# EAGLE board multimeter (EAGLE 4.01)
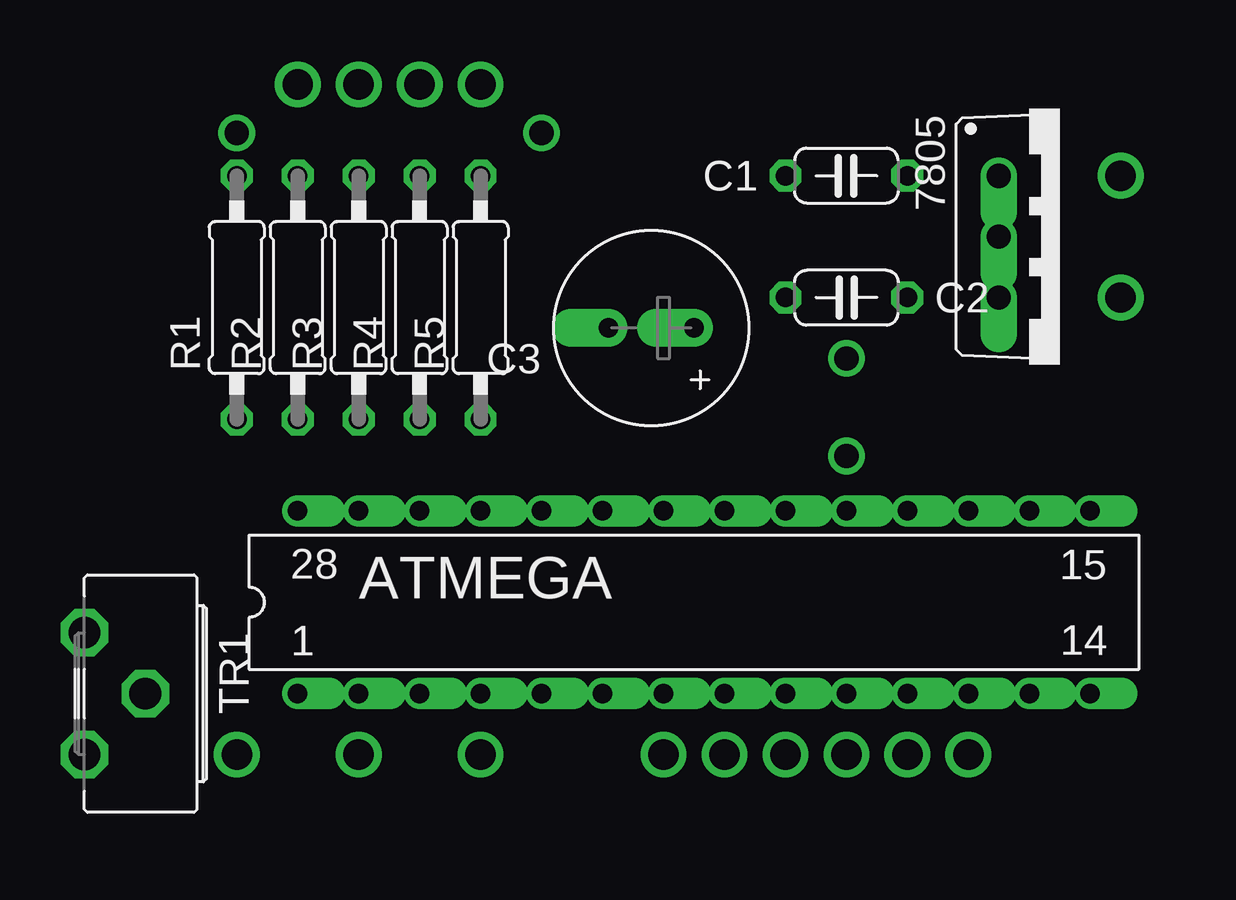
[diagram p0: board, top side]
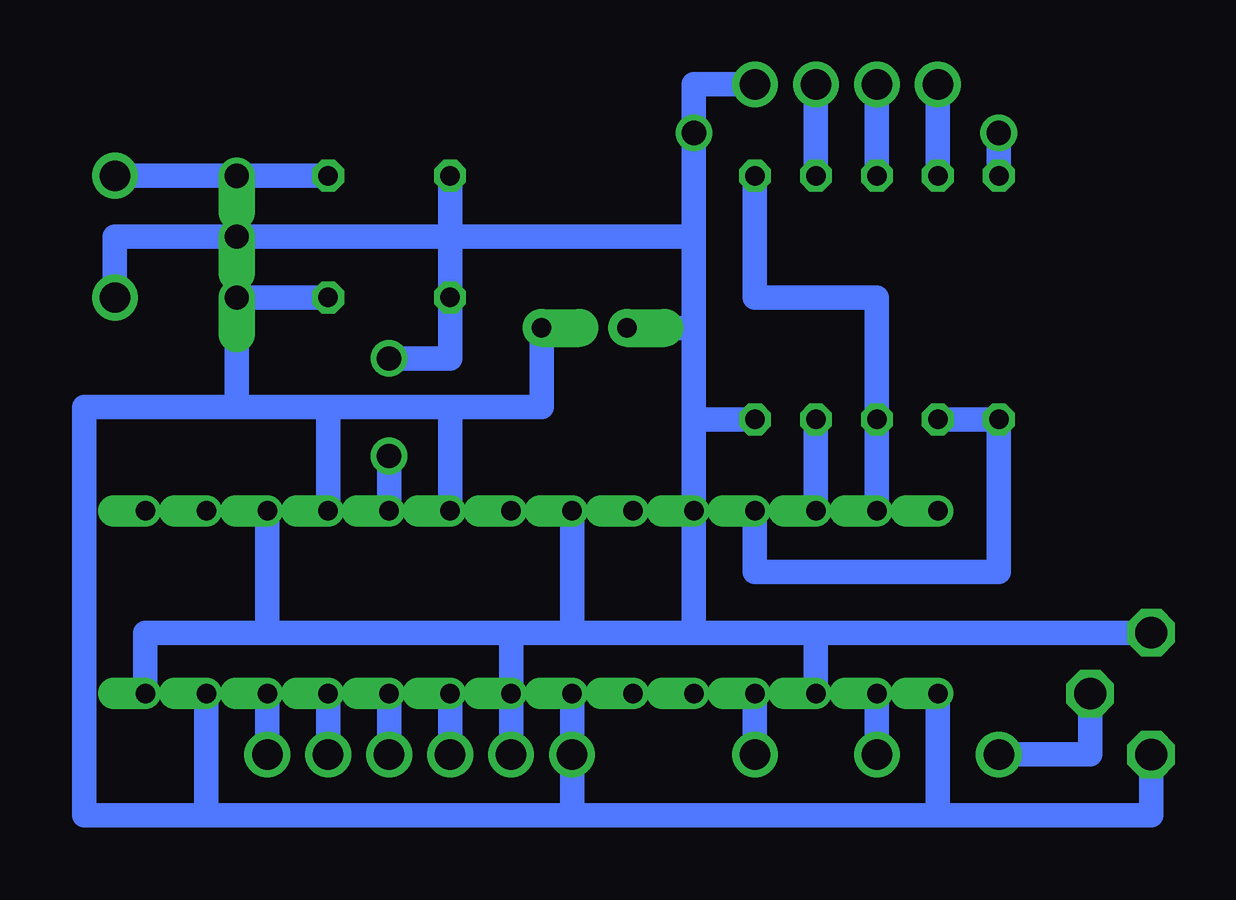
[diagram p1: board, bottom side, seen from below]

No outline drawn. Coordinates in mm, seen from the top.
Copper layers used: Bottom

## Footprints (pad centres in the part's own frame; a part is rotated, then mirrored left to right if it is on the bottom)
TO220V = drill 1.016 offset: 1 -2.54,-2.54; 2 0,-2.54; 3 2.54,-2.54
DIL28-3 = drill 0.813 offset: 1 -16.51,-3.81; 2 -13.97,-3.81; 3 -11.43,-3.81; 4 -8.89,-3.81; 5 -6.35,-3.81; 6 -3.81,-3.81; 7 -1.27,-3.81; 8 1.27,-3.81; 9 3.81,-3.81; 10 6.35,-3.81; 11 8.89,-3.81; 12 11.43,-3.81; 13 13.97,-3.81; 14 16.51,-3.81; 15 16.51,3.81; 16 13.97,3.81; 17 11.43,3.81; 18 8.89,3.81; 19 6.35,3.81; 20 3.81,3.81; 21 1.27,3.81; 22 -1.27,3.81; 23 -3.81,3.81; 24 -6.35,3.81; 25 -8.89,3.81; 26 -11.43,3.81; 27 -13.97,3.81; 28 -16.51,3.81
C050-024X044 = drill 0.813 octagon: 1 -2.54,0; 2 2.54,0
E3,5-8E = drill 0.813 pad 1.575 offset: + -1.778,0; - 1.778,0
0207/10 = drill 0.813 octagon: 1 -5.08,0; 2 5.08,0
CA9H = drill 1.321 octagon: 1 -2.54,0; 2 0,2.54; 3 2.54,0

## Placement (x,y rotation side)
7805  [TO220V]  64.77,62.23 270 top
ATMEGA  [DIL28-3]  49.53,46.99 0 top
C1  [C050-024X044]  55.88,64.77 180 top
C2  [C050-024X044]  55.88,59.69 0 top
C3  [E3,5-8E]  47.75,58.42 180 top
R1  [0207/10]  30.48,59.69 90 top
R2  [0207/10]  33.02,59.69 90 top
R3  [0207/10]  35.56,59.69 90 top
R4  [0207/10]  38.1,59.69 90 top
R5  [0207/10]  40.64,59.69 90 top
TR1  [CA9H]  24.13,43.18 270 top

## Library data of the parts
7805 = transistor-npn
ATMEGA = 74ac-logic
C1-C3 R1-R5 = rcl
TR1 = pot

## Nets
S$1: ATMEGA.2
S$2: ATMEGA.4
S$3: ATMEGA.12
S$4: ATMEGA.11
S$5: ATMEGA.10
S$6: ATMEGA.9
S$7: R2.2
S$8: R1.2
S$9: ATMEGA.27 R3.1 R5.2
S$10: ATMEGA.26 R4.1
S$11: R3.2
S$12: R4.2
S$13: 7805.2 ATMEGA.3 ATMEGA.8 ATMEGA.14 ATMEGA.17 ATMEGA.22 ATMEGA.24 C1.2 C2.1 R5.1 TR1.1
S$14: 7805.1 C1.1
S$15: 7805.3 ATMEGA.1 ATMEGA.7 ATMEGA.13 ATMEGA.18 ATMEGA.20 C2.2 C3.+ TR1.3
S$16: ATMEGA.25 R2.1
S$17: ATMEGA.19
S$18: TR1.2

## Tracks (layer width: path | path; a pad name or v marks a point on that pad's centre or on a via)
S$1  (via drill 1.27)
  Bottom 1.016: ATMEGA.2 v35.56,40.64
S$2  (via drill 1.27)
  Bottom 1.016: ATMEGA.4 v40.64,40.64
S$3  (via drill 1.27)
  Bottom 1.016: ATMEGA.12 v60.96,40.64
S$4  (via drill 1.27)
  Bottom 1.016: ATMEGA.11 v58.42,40.64
S$5  (via drill 1.27)
  Bottom 1.016: ATMEGA.10 v55.88,40.64
S$6  (via drill 1.27)
  Bottom 1.016: ATMEGA.9 v53.34,40.64
S$7  (via drill 1.27)
  Bottom 1.016: v33.02,68.58 R2.2
S$8  (via drill 1.02)
  Bottom 1.016: v30.48,66.55 R1.2
S$9
  Bottom 1.016: ATMEGA.27 R3.1 35.56,59.69 40.64,59.69 R5.2
S$10
  Bottom 1.016: R4.1 ATMEGA.26
S$11  (via drill 1.27)
  Bottom 1.016: v35.56,68.58 R3.2
S$12  (via drill 1.27)
  Bottom 1.016: v38.1,68.58 R4.2
S$13  (via drill 1.02, 1.27)
  Bottom 1.016: v67.31,59.69 67.31,62.23 7805.2 53.34,62.23 | v40.64,68.58 43.18,68.58 v43.18,66.55 43.18,62.23 | ATMEGA.14 66.04,45.72 60.96,45.72 | 53.34,62.23 C1.2 | 43.18,62.23 53.34,62.23 | v50.8,40.64 ATMEGA.8 50.8,45.72 | 60.96,45.72 ATMEGA.17 | 50.8,45.72 60.96,45.72 | 43.18,54.61 R5.1 | 43.18,54.61 43.18,58.42 | 43.18,58.42 43.18,62.23 | 43.18,54.61 ATMEGA.24 43.18,45.72 | 48.26,45.72 50.8,45.72 | 48.26,45.72 ATMEGA.22 | 43.18,45.72 48.26,45.72 | 38.1,45.72 43.18,45.72 | 38.1,45.72 ATMEGA.3 | TR1.1 38.1,45.72 | C2.1 53.34,62.23 | 45.72,58.42 43.18,58.42
S$14  (via drill 1.27)
  Bottom 1.016: C1.1 7805.1 v67.31,64.77
S$15  (via drill 1.27)
  Bottom 1.016: 53.34,55.12 ATMEGA.20 | 58.42,55.12 ATMEGA.18 | 58.42,55.12 53.34,55.12 | 62.23,55.12 58.42,55.12 | 62.23,55.12 7805.3 C2.2 | 62.23,55.12 68.58,55.12 68.58,38.1 63.5,38.1 | ATMEGA.7 v48.26,40.64 48.26,38.1 | 63.5,38.1 ATMEGA.13 | 48.26,38.1 63.5,38.1 | 33.02,38.1 48.26,38.1 | 33.02,38.1 ATMEGA.1 | TR1.3 24.13,38.1 33.02,38.1 | C3.+ 49.53,55.12 53.34,55.12
S$16
  Bottom 1.016: R2.1 30.48,54.61 30.48,48.26 40.64,48.26 ATMEGA.25
S$17  (via drill 1.02)
  Bottom 1.016: v55.88,53.09 ATMEGA.19
S$18  (via drill 1.27)
  Bottom 1.016: v30.48,40.64 26.67,40.64 TR1.2
S$19  (via drill 1.02)
  Bottom 1.016: v55.88,57.15 53.34,57.15 53.34,59.44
